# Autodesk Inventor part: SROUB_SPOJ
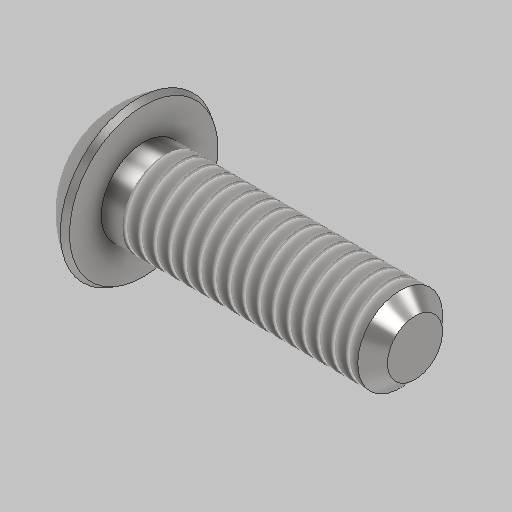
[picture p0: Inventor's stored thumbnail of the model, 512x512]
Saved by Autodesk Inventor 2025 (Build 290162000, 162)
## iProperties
Created: 2025-02
Part Number: SROUB_SPOJ
Material: Stainless Steel
Document SubType Name: Modeling
Designer: dansp
Mass: 1.70818 g
Surface Area: 2.67125 cm^2
Volume: 0.213522 cm^3
Density: 8 g/cm^3
Appearance: Semi-Polished
Author: dansp
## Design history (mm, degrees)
sketch "Sketch1"
  geometry: L1 (0, 5.084)-(0, -2.329) reference; L2 (-3.301, 0)-(18.05, 0) reference; L3 (0, 0)-(0, 3.8); L4 (0, 3.8)-(2.2, 3.8); L5 (2.2, 3.8)-(2.2, 2); L6 (2.2, 2)-(15, 2); L7 (15, 2)-(15, 0); L8 (0, 0)-(15, 0); A1 r 4.191 centre (3.968, 0) between (2.2, 3.8) and (0, 1.35); 1 further point
  constraints: 12 end point, 4 point on line, 3 perpendicular, 2 point on circle, 1 centre point, 1 collinear, 1 horizontal
  dimensions: "d0" = 15 distance between parallel lines of L7 L1; "d1" = 7.6 diameter of L4 L2; "d2" = 4 diameter of L6 L2; "d3" = 2.2 distance between parallel lines of L5 L1; "d4" = 2.7 diameter of A1.end L2
revolve "Revolution1" sketch "Sketch1" stored, may be unused: angle "d5" = 90 deg
chamfer "Chamfer1" distance "d6" = 0.3; stored, may be unused: second distance "d7" = 2, angle "d8" = 45 deg
thread "Thread1" dims "d9" = 12.8, "d10" = 1
chamfer "Chamfer2" distance "d11" = 0.7; stored, may be unused: second distance "d12" = 2, angle "d13" = 45 deg
sketch "Sketch2"
  geometry: L1 (0, 5.32)-(0, -5.32) reference; L2 (-5.32, 0)-(5.32, 0) reference; L3 (0, 1.27)-(1.1, 0.635); L4 (1.1, 0.635)-(1.1, -0.635); L5 (1.1, -0.635)-(0, -1.27); L6 (0, -1.27)-(-1.1, -0.635); L7 (-1.1, -0.635)-(-1.1, 0.635); L8 (-1.1, 0.635)-(0, 1.27); 2 further points
  constraints: 12 end point, 1 coincident, 1 point on line, 13 other
  dimensions: "d14" = 2.2 distance between parallel lines of L4 L7
extrude "Extrusion1" cut sketch "Sketch2" distance "d15" = 1.3; taper "d16" = 0 deg
body "Solid1"
